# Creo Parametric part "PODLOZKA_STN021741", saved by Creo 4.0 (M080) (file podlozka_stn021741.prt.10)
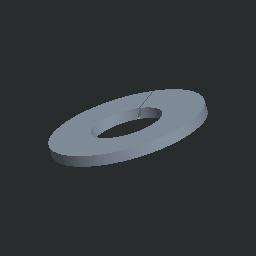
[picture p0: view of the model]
Units: Custom; MM, KILOGRAM, SECS
Materials in the file: OCEL_N

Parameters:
  KATEGORIE = "4"
  NAZOV = "PODLOZKA_STN021741"
  NORMA = "STN 02 1741"
  N2 = "_"
  NAZOV_1 = "START_PART_IPM"
  PTC_MATERIAL_NAME = "OCEL_N"

Other parameters: HMOTNOST, HUSTOTA, HMOTNOST_1, D4, D6

Created from: STN_021741_PODLOZKA_PRUZNA_OBDL.PRT

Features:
  1. datum plane "DTM1"
  2. cut

Layers: BEZUGSACHSEN, BEZUGSEBENEN, BOHRUNGEN, KONSTRUKTIONSELEMENTE, NORMTEILE

Family table entries: GENERIC, PODLOZKA_3, PODLOZKA_STN021741, value(d_val), value(i_val), PODLOZKA_4, PODLOZKA_STN021741, PODLOZKA_5, PODLOZKA_STN021741, PODLOZKA_6, PODLOZKA_STN021741, PODLOZKA_8, PODLOZKA_STN021741, PODLOZKA_10, PODLOZKA_STN021741, PODLOZKA_12, PODLOZKA_STN021741, PODLOZKA_16, PODLOZKA_STN021741, PODLOZKA_20, PODLOZKA_STN021741, PODLOZKA_24, PODLOZKA_STN021741, PODLOZKA_30, PODLOZKA_STN021741, # Pro/TABLE, [] S 92;, [] W 10;, [A] W  3;, [B] W 12;, [C] W 10;, [D] W 10;, [E] W 10;

Surfaces: 6 plane, 2 cylinder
